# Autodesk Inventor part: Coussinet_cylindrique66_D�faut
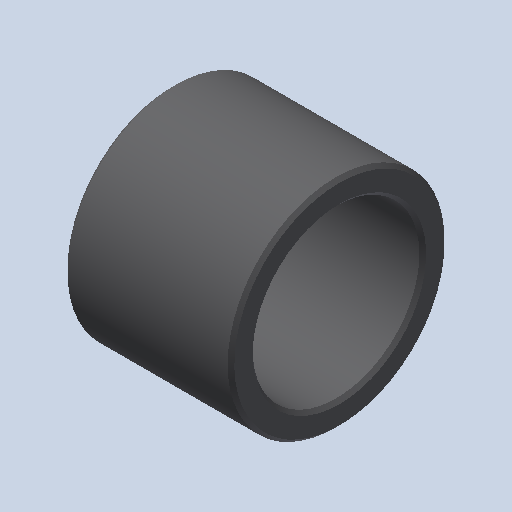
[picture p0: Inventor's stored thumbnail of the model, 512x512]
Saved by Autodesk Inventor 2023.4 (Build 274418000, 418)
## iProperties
Created: 2011-01
Part Number: Coussinet_cylindrique66_D�faut
Document SubType Name: Modeling
Designer: eric
Density: 1 g/cm^3
Mass: 4.31228 g
Surface Area: 32.5608 cm^2
Volume: 4.31228 cm^3
Material: Générique
Appearance: Yellow
Author: eric
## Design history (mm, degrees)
feature "Base1"
node "Corps solides"
node "Corps surfaciques"
node "Solide1"
